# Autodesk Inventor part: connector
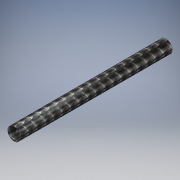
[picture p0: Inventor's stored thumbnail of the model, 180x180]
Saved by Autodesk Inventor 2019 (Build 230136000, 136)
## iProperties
Created: 2020-02
Part Number: connector
Material: Generic
Document SubType Name: Modeling
Designer: shivu
Density: 1 g/cm^3
Appearance: Engine Turned
Author: shivu
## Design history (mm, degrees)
sketch "Sketch1"
  geometry: C1 r 1.5 at (0, 0); C2 r 1.505 at (0, 0); 1 further point
  constraints: 2 centre point, 2 coincident
  dimensions: "d0" = 3 diameter of C1; "d1" = 3.01 diameter of C2
extrude "Extrusion1" new body sketch "Sketch1" distance "d2" = 35.537; taper "d3" = 0 deg
body "Solid1"
